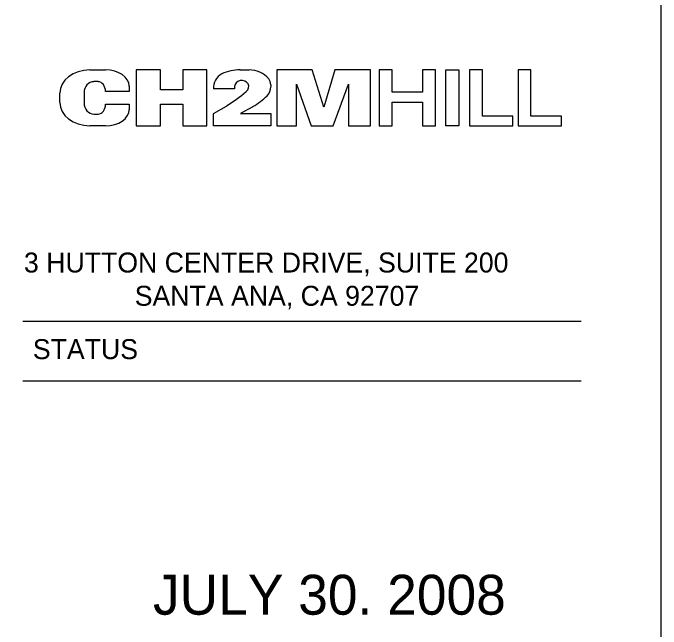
# Model space of a CAD drawing. Extents: x 0 to 3.5, y -0.08 to 2.5.
# Drawn here: x 3.1615 to 3.5, y 1.2155 to 1.5371 of the extents above; entities that cross this region are included whole.
import ezdxf

# ---------------------------------------------------------------- set-up
doc = ezdxf.new("R2010")
doc.units = 0
for name, color, linetype in [('G-ANNO-TTLB', 7, 'Continuous'), ('G-ANNO-TTLB-NFCR', 7, 'Continuous'), ('G-TTLB-LOGO', 7, 'Continuous'), ('G-TTLB-OTLN', 7, 'Continuous')]:
    doc.layers.add(name, color=color, linetype=linetype)

msp = doc.modelspace()

# ---------------------------------------------------------------- linework, layer by layer
at = {"layer": 'G-ANNO-TTLB'}
msp.add_line((3.16667, 1.34505), (3.45833, 1.34505), dxfattribs=at)
msp.add_lwpolyline([(3.16667, 1.3763), (3.45833, 1.3763)], dxfattribs=at)
at = {"layer": 'G-TTLB-LOGO'}
for p, q in [((3.20165, 1.50736), (3.20173, 1.50736)), ((3.20173, 1.50736), (3.20982, 1.50736)), ((3.28015, 1.50736), (3.28482, 1.50736)), ((3.20598, 1.50128), (3.20365, 1.50128)), ((3.22215, 1.49903), (3.22215, 1.49619)), ((3.27723, 1.49753), (3.26623, 1.49753)), ((3.27723, 1.49869), (3.27723, 1.49753)), ((3.29615, 1.49969), (3.29615, 1.49869)), ((3.29615, 1.49969), (3.29615, 1.49969)), ((3.1859, 1.49036), (3.1859, 1.49519)), ((3.19865, 1.49553), (3.19865, 1.49003)), ((3.22215, 1.49619), (3.20982, 1.49611)), ((3.20982, 1.48953), (3.22215, 1.48944)), ((3.22215, 1.48944), (3.22215, 1.48661)), ((3.26623, 1.48469), (3.27298, 1.48853)), ((3.28682, 1.48819), (3.2804, 1.48469)), ((3.20365, 1.48436), (3.20598, 1.48436)), ((3.20982, 1.47819), (3.20165, 1.47819))]:
    msp.add_line(p, q, dxfattribs=at)
for points in [[(3.2259, 1.50736), (3.2259, 1.47819), (3.23857, 1.47819), (3.23857, 1.48944), (3.25015, 1.48944), (3.25015, 1.47819), (3.26265, 1.47819), (3.26265, 1.50736), (3.25015, 1.50736), (3.25015, 1.49694), (3.23857, 1.49694), (3.23857, 1.50736)], [(3.29923, 1.50736), (3.29923, 1.47819), (3.30965, 1.47819), (3.30965, 1.50003), (3.31715, 1.47819), (3.32865, 1.47819), (3.33682, 1.50003), (3.33682, 1.47819), (3.34823, 1.47819), (3.34823, 1.50736), (3.32957, 1.50736), (3.32382, 1.48794), (3.31782, 1.50736)], [(3.35273, 1.50736), (3.35273, 1.47819), (3.35948, 1.47819), (3.35948, 1.49061), (3.3754, 1.49061), (3.3754, 1.47819), (3.38215, 1.47819), (3.38215, 1.50736), (3.3754, 1.50736), (3.3754, 1.49586), (3.35948, 1.49586), (3.35948, 1.50736)], [(3.38757, 1.50736), (3.3944, 1.50736), (3.3944, 1.47819), (3.38757, 1.47819)], [(3.39998, 1.50736), (3.39998, 1.47819), (3.42265, 1.47819), (3.42265, 1.48319), (3.40673, 1.48319), (3.40673, 1.50736)], [(3.42532, 1.50736), (3.42532, 1.47819), (3.44798, 1.47819), (3.44798, 1.48319), (3.43207, 1.48319), (3.43207, 1.50736)]]:
    msp.add_lwpolyline(points, close=True, dxfattribs=at)
msp.add_lwpolyline([(3.2804, 1.48469), (3.29623, 1.48469), (3.29623, 1.47819), (3.26623, 1.47819), (3.26623, 1.48453)], dxfattribs=at)
for centre, major_axis, ratio, start_param, end_param in [((3.2017, 1.49523), (-0.01576, 0), 0.771028, 4.713205, 6.283068), ((3.2098, 1.49895), (0.01237, 0), 0.681723, 0.000928, 1.570692), ((3.28012, 1.48379), (0, 0.0236), 0.994949, 0, 0.422278), ((3.28484, 1.49352), (0, 0.01386), 0.994949, 5.445039, 6.283185), ((3.27442, 1.49805), (0, -0.00826), 0.994949, 3.639774, 4.783669), ((3.20362, 1.49552), (0, 0.00572), 0.875758, 6.279551, 7.852871), ((3.20597, 1.49609), (0, 0.00515), 0.744108, 4.715462, 6.281546), ((3.28095, 1.49865), (-0.00368, 0), 0.884467, 2.263401, 6.281821), ((3.29075, 1.49961), (0, 0.0054), 0.994949, 4.726087, 5.342192), ((3.28979, 1.49847), (0, 0.00637), 0.994949, 3.913176, 4.739837), ((3.23308, 1.55454), (0, -0.0772), 0.994949, 0.546504, 0.712786), ((3.26614, 1.52335), (0, -0.04078), 0.994949, 0.535616, 0.764125), ((3.2017, 1.49037), (0.01576, 0), 0.771028, 3.14171, 4.711573), ((3.20362, 1.49008), (0, -0.00572), 0.875758, 4.7135, 6.28682), ((3.20597, 1.48951), (0, 0.00515), 0.744108, 3.143232, 4.709316), ((3.2098, 1.48665), (0.01237, 0), 0.681723, 4.712493, 6.282257)]:
    msp.add_ellipse(centre, major_axis=major_axis, ratio=ratio, start_param=start_param, end_param=end_param, dxfattribs=at)
at = {"layer": 'G-TTLB-OTLN'}
msp.add_lwpolyline([(0, 0), (3.5, 0), (3.5, 2.5), (0, 2.5)], close=True, dxfattribs=at)

# ---------------------------------------------------------------- texts
at = {"layer": 'G-ANNO-TTLB'}
msp.add_text('STATUS', height=0.010417, dxfattribs=at).set_placement((3.17183, 1.35643))
at = {"layer": 'G-ANNO-TTLB-NFCR'}
msp.add_text('JULY 30. 2008', height=0.0208333, dxfattribs=at).set_placement((3.23461, 1.22302))
at = {"layer": 'G-TTLB-LOGO'}
for s, p in [('3 HUTTON CENTER DRIVE, SUITE 200', (3.1672, 1.40164)), ('SANTA ANA, CA 92707', (3.22506, 1.38428))]:
    msp.add_text(s, height=0.0104167, rotation=0, dxfattribs=at).set_placement(p)

doc.saveas('drawing.dxf')
